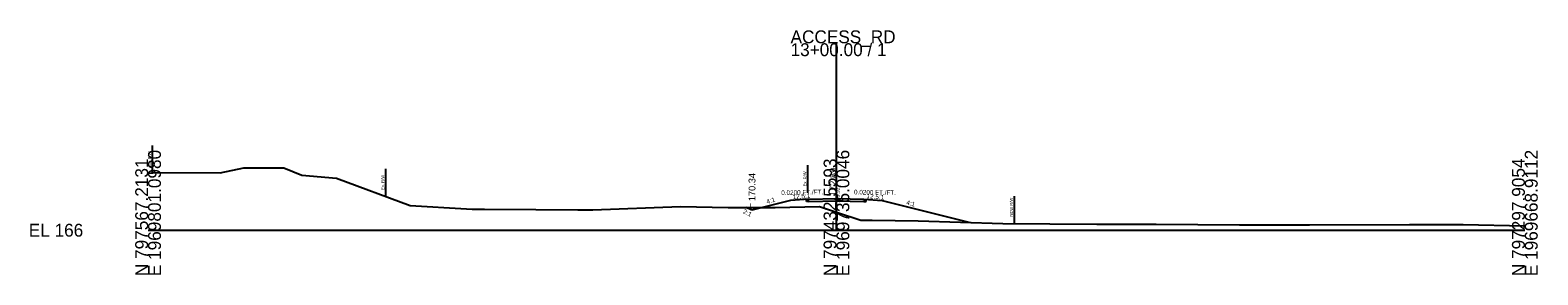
# Model space of a CAD drawing. Extents: x 27306 to 1891059, y 5381 to 776288.
# Drawn here: x 27306 to 27634.5, y 7380.7 to 7434 of the extents above; entities that cross this region are included whole.
import ezdxf

# ---------------------------------------------------------------- set-up
doc = ezdxf.new("R2010")
doc.units = 0
for name, color, linetype in [('RD_EX_BldgApp', 7, 'Continuous'), ('RD_EX_H2O_BlueLn', 7, 'Continuous'), ('RD_EX_RailRoad', 7, 'Continuous'), ('RD_HC_Cl', 7, 'Continuous'), ('RD_HC_Data', 7, 'Continuous'), ('RD_HC_Data_Tic', 7, 'Continuous'), ('RD_HC_TX_Sta50', 7, 'Continuous'), ('RD_PD_ALT2_CL', 7, 'Continuous'), ('RD_PD_ALT3_CL', 7, 'Continuous'), ('RD_PD_ALT5_CL', 7, 'Continuous'), ('RD_PD_Final_Cl', 7, 'Continuous'), ('RD_PD_Final_TrvlWay', 7, 'Continuous'), ('RD_PD_MedBWall', 7, 'Continuous'), ('RD_TX_Misc2', 7, 'Continuous'), ('RD_TX_RoadID', 7, 'Continuous')]:
    doc.layers.add(name, color=color, linetype=linetype)

msp = doc.modelspace()

# ---------------------------------------------------------------- linework, layer by layer
at = {"layer": 'RD_EX_H2O_BlueLn'}
for p, q in [((27475.64, 7397.21), (27471.64, 7396.89)), ((27487.64, 7397.21), (27491.64, 7396.89))]:
    msp.add_line(p, q, dxfattribs=at)
at = {"layer": 'RD_EX_RailRoad'}
for p, q in [((27475.14, 7396.95), (27475.64, 7396.96)), ((27475.14, 7396.7), (27475.14, 7396.95)), ((27475.64, 7396.71), (27475.14, 7396.7)), ((27475.64, 7396.96), (27475.64, 7397.21)), ((27475.64, 7396.71), (27481.65, 7396.83)), ((27481.65, 7396.83), (27487.64, 7396.71)), ((27487.64, 7396.96), (27487.64, 7397.21)), ((27488.14, 7396.95), (27487.64, 7396.96)), ((27487.64, 7396.71), (27488.14, 7396.7)), ((27488.14, 7396.7), (27488.14, 7396.95))]:
    msp.add_line(p, q, dxfattribs=at)
at = {"layer": 'RD_HC_Cl'}
for p, q in [((27481.65, 7390.44), (27481.65, 7431.11)), ((27331.65, 7390.44), (27481.65, 7390.44)), ((27481.65, 7390.44), (27631.65, 7390.44))]:
    msp.add_line(p, q, dxfattribs=at)
at = {"layer": 'RD_PD_ALT5_CL'}
for p, q in [((27463.2, 7394.77), (27461.98, 7395.38)), ((27471.64, 7396.89), (27463.2, 7394.77)), ((27491.64, 7396.89), (27510.79, 7392.1))]:
    msp.add_line(p, q, dxfattribs=at)
at = {"layer": 'RD_PD_Final_Cl'}
msp.add_lwpolyline([(27331.65, 7402.85), (27333.74, 7402.97), (27347.34, 7402.91), (27352.5, 7403.99), (27361.22, 7403.99), (27365.17, 7402.39), (27372.71, 7401.76), (27388.74, 7395.8), (27401, 7395.09), (27402.3, 7395), (27404.95, 7395.03), (27416.11, 7394.94), (27425.3, 7394.86), (27427.91, 7394.84), (27428.56, 7394.84), (27447.66, 7395.63), (27458.05, 7395.37), (27468.26, 7395.4), (27477.98, 7395.61), (27481.65, 7394.35), (27486.94, 7392.63), (27489.44, 7392.66), (27499.47, 7392.45), (27517.91, 7391.87), (27538.4, 7391.79), (27547.08, 7391.77), (27551.34, 7391.77), (27569.49, 7391.63), (27584.75, 7391.6), (27606.49, 7391.7), (27614.33, 7391.72), (27618.18, 7391.7), (27631.65, 7391.42)], dxfattribs=at)
at = {"layer": 'RD_PD_Final_TrvlWay'}
for p, q in [((27332.53, 7408.9), (27332.53, 7402.9)), ((27383.36, 7403.82), (27383.36, 7397.82)), ((27475.36, 7404.56), (27475.36, 7398.56))]:
    msp.add_line(p, q, dxfattribs=at)
at = {"layer": 'RD_PD_MedBWall'}
for p, q in [((27475.64, 7397.21), (27481.65, 7397.33)), ((27481.65, 7397.33), (27487.64, 7397.21))]:
    msp.add_line(p, q, dxfattribs=at)
at = {"layer": 'RD_TX_Misc2'}
msp.add_line((27487.64, 7397.21), (27491.64, 7396.89), dxfattribs=at)
at = {"layer": 'RD_TX_RoadID'}
msp.add_line((27520.36, 7397.86), (27520.36, 7391.86), dxfattribs=at)

# ---------------------------------------------------------------- texts
at = {"layer": 'RD_EX_BldgApp'}
msp.add_text('169.92', height=0.8, rotation=90, dxfattribs=at).set_placement((27482.35, 7396.37))
at = {"layer": 'RD_HC_Cl'}
for s, p in [('ACCESS_RD', (27471.65, 7431.11)), ('13+00.00 / 1', (27471.65, 7428.31)), ('EL 166', (27305.65, 7389.04))]:
    msp.add_text(s, height=2.8, dxfattribs=at).set_placement(p)
for s, p in [('N 797567.2131', (27331.65, 7380.44)), ('E 1969801.0980', (27334.45, 7380.44)), ('N 797432.5593', (27481.65, 7380.44)), ('E 1969735.0046', (27484.45, 7380.44)), ('N 797297.9054', (27631.65, 7380.44)), ('E 1969668.9112', (27634.45, 7380.44))]:
    msp.add_text(s, height=2.8, rotation=90, dxfattribs=at).set_placement(p)
at = {"layer": 'RD_HC_Data'}
msp.add_text(' 172.89', height=1.5, rotation=90, dxfattribs=at).set_placement((27481.65, 7397.33))
at = {"layer": 'RD_HC_Data_Tic'}
for rotation, p in [(4.5739, (27472.14, 7397.18)), (355.4261, (27488.18, 7397.41))]:
    msp.add_text('12.5:1', height=1, rotation=rotation, dxfattribs=at).set_placement(p)
at = {"layer": 'RD_HC_TX_Sta50'}
for s, rotation, p in [('0.0200 FT./FT.', 1.1458, (27469.63, 7398.09)), ('0.0200 FT./FT.', 358.8542, (27485.47, 7398.25)), ('4:1', 15.5821, (27466.53, 7396.16)), ('4:1', 344.4179, (27496.78, 7396.07)), ('2:1', 333.435, (27461.17, 7394.2))]:
    msp.add_text(s, height=1, rotation=rotation, dxfattribs=at).set_placement(p)
at = {"layer": 'RD_PD_ALT2_CL'}
msp.add_text('170.34', height=1.5, rotation=90, dxfattribs=at).set_placement((27464, 7396.76))
at = {"layer": 'RD_PD_ALT3_CL'}
msp.add_text('L', height=1.5, dxfattribs=at).set_placement((27462.69, 7394.77))
at = {"layer": 'RD_PD_Final_TrvlWay'}
for p in [(27332.28, 7404.28), (27383.11, 7399.2), (27475.11, 7399.95)]:
    msp.add_text('Ex. R/W ', height=0.65, rotation=90, dxfattribs=at).set_placement(p)
at = {"layer": 'RD_TX_RoadID'}
msp.add_text('NEW R/W ', height=0.65, rotation=90, dxfattribs=at).set_placement((27520.09, 7393.42))

doc.saveas('drawing.dxf')
